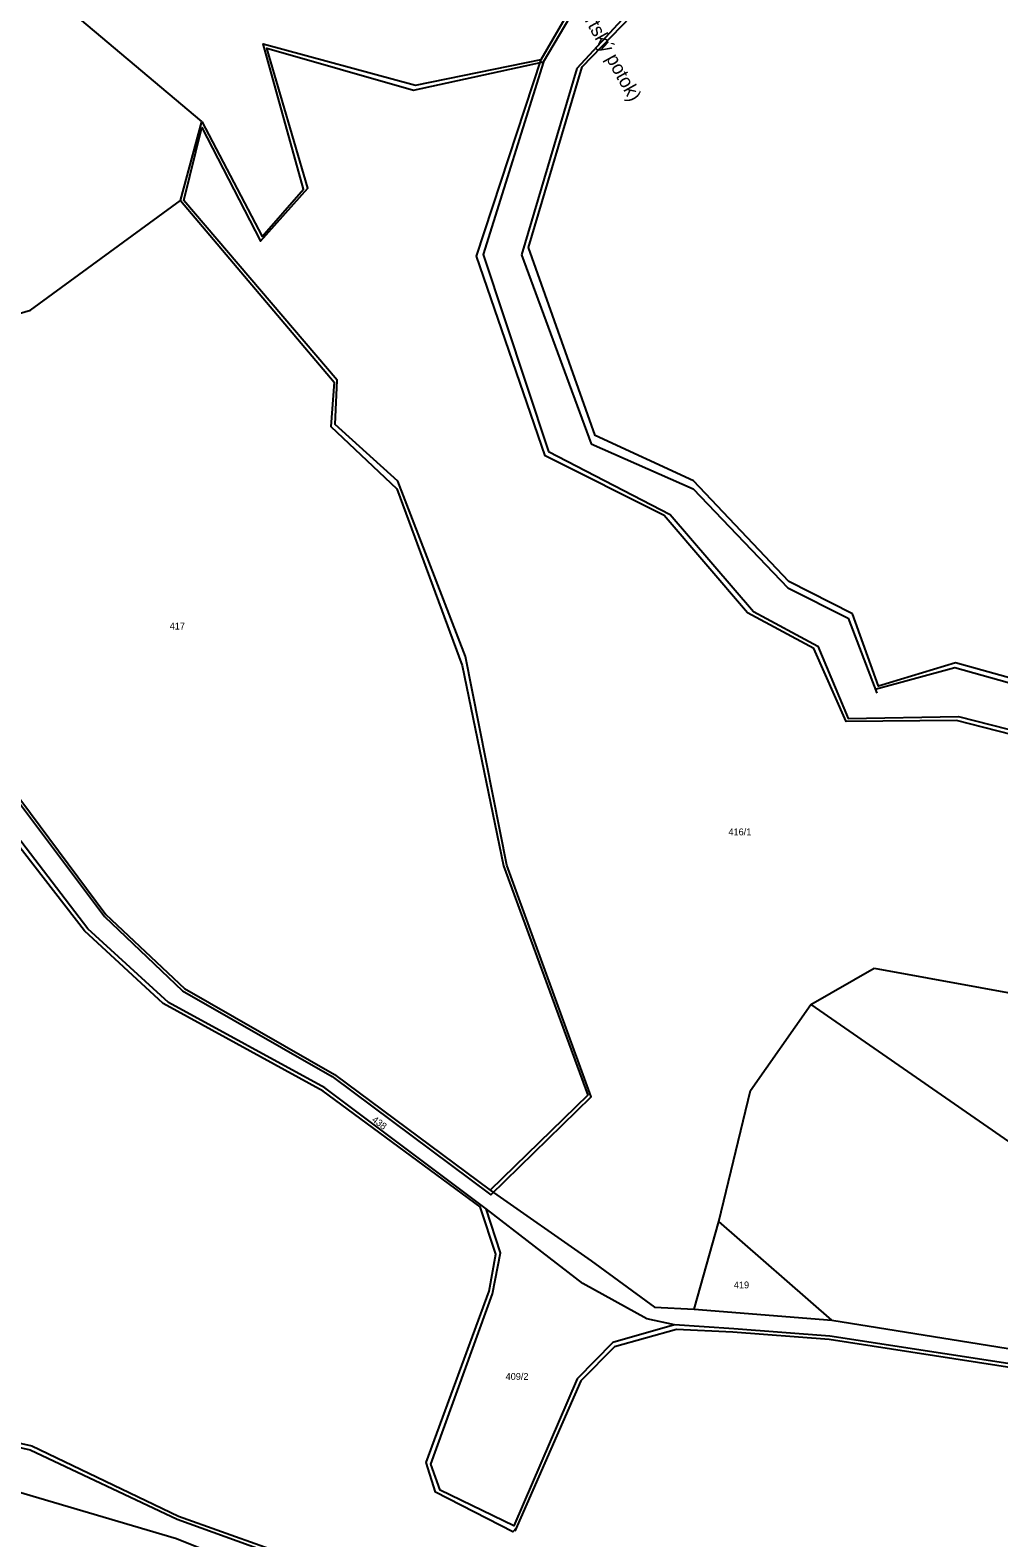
# Model space of a CAD drawing. Extents: x -880531 to -877616, y -1023932 to -1021350.
# Drawn here: x -880041.3 to -879800.4, y -1022593.9 to -1022219 of the extents above; entities that cross this region are included whole.
import ezdxf

# ---------------------------------------------------------------- set-up
doc = ezdxf.new("R2010")
doc.units = 0
for name, color, linetype in [('Hranice parcel', 7, 'Continuous'), ('Parcelní čísla', 7, 'Continuous'), ('Pop  PČ popisy', 7, 'Continuous'), ('Vnitřní kresba', 7, 'Continuous')]:
    doc.layers.add(name, color=color, linetype=linetype)

msp = doc.modelspace()

# ---------------------------------------------------------------- linework, layer by layer
at = {"layer": 'Hranice parcel'}
for p, q in [((-880003.96, -1022261.33), (-879998.66, -1022241.71)), ((-879836.8, -1022364.1), (-879852.62, -1022356.1)), ((-879876.21, -1022537.01), (-879870.02, -1022515.23)), ((-879841.96, -1022539.75), (-879870.02, -1022515.23)), ((-879876.21, -1022537.01), (-879841.96, -1022539.75))]:
    msp.add_line(p, q, dxfattribs=at)
for points in [[(-879998.66, -1022241.71), (-880052.08, -1022196.68), (-880086.25, -1022160.89), (-880089.28, -1022150.93), (-880085.05, -1022135.52)], [(-879852.62, -1022356.1), (-879876.34, -1022331.08), (-879900.8, -1022319.74), (-879917.41, -1022273.06), (-879904.07, -1022228.12), (-879891.86, -1022215.5), (-879913.95, -1022179.12), (-879927.16, -1022162.97), (-879953.53, -1022160.38), (-879979.51, -1022142.78), (-880011, -1022145.56), (-880011.84, -1022139.78)], [(-879914.25, -1022226.31), (-879906.81, -1022213.47), (-879922.39, -1022185.03), (-879929.69, -1022178.8), (-879958.73, -1022168.9), (-879984.23, -1022153.64), (-880001.2, -1022153.91)], [(-879998.66, -1022241.71), (-879983.68, -1022270.28), (-879973.36, -1022258.52), (-879983.36, -1022222.39), (-879945.5, -1022232.64), (-879914.25, -1022226.31)], [(-879633.8, -1022480.63), (-879660.6, -1022471.88), (-879677.81, -1022467.72), (-879699.12, -1022454.05), (-879720.69, -1022446.04), (-879736.48, -1022420.52), (-879771.92, -1022408.58), (-879783.4, -1022397.72), (-879810.92, -1022390.65), (-879838.37, -1022390.91), (-879846.45, -1022372.72), (-879862.92, -1022363.84), (-879883.64, -1022339.68), (-879913.23, -1022324.87), (-879930.34, -1022275.22), (-879914.25, -1022226.31)], [(-880095.42, -1022304.53), (-880041.25, -1022288.65), (-880003.96, -1022261.33)], [(-880003.96, -1022261.33), (-879965.77, -1022306.53), (-879966.58, -1022317.51), (-879950.15, -1022333.01), (-879933.89, -1022376.93), (-879923.6, -1022426.78), (-879902.64, -1022483.8), (-879926.96, -1022507.44)], [(-879927.95, -1022512.07), (-879968.07, -1022481.99), (-880006.9, -1022460.74), (-880027.04, -1022442.45), (-880059.05, -1022400.63), (-880086.76, -1022384.28), (-880123.5, -1022378.49), (-880154.72, -1022371.67), (-880202.4, -1022363.81)], [(-879770.1, -1022387.72), (-879811.18, -1022376.32), (-879830.38, -1022382.07), (-879836.8, -1022364.1)], [(-880120.79, -1022373.06), (-880085.05, -1022378.77), (-880053.08, -1022397.83), (-880022.5, -1022438.88), (-880002.99, -1022457.32), (-879965.63, -1022478.64), (-879926.96, -1022507.44)], [(-879870.02, -1022515.23), (-879862.14, -1022482.62), (-879847.14, -1022461.29)], [(-879847.14, -1022461.29), (-879797.97, -1022495.32), (-879652.28, -1022517.43)], [(-879926.96, -1022507.44), (-879901.83, -1022525.04), (-879886.09, -1022536.57), (-879876.21, -1022537.01)], [(-879881.1, -1022540.95), (-879896.44, -1022545.28), (-879905.27, -1022554.37), (-879921.06, -1022590.94), (-879939.38, -1022582.03), (-879941.72, -1022575.56), (-879926.35, -1022533.25), (-879924.39, -1022523), (-879927.95, -1022512.07)], [(-879881.1, -1022540.95), (-879888, -1022539.4), (-879903.88, -1022530.65), (-879927.95, -1022512.07)], [(-879700.32, -1022565.93), (-879708.74, -1022562.21), (-879723.29, -1022560.15), (-879752.61, -1022558.22), (-879785.23, -1022552.56), (-879842.49, -1022543.71), (-879866.35, -1022541.91), (-879881.1, -1022540.95)], [(-879841.96, -1022539.75), (-879784.65, -1022548.98), (-879752.14, -1022555.09), (-879721.69, -1022556.28), (-879706.73, -1022558.11), (-879695.24, -1022559.41), (-879680.86, -1022572.57), (-879675.16, -1022576.16)], [(-880166.5, -1022548.2), (-880166.5, -1022563), (-880091.71, -1022568.45), (-880004.96, -1022594.04), (-879942.81, -1022618.93)], [(-880109.86, -1022556.49), (-880041.33, -1022572.02), (-880004.82, -1022589.23), (-879971.92, -1022601.09), (-879941.5, -1022616.12)]]:
    msp.add_lwpolyline(points, dxfattribs=at)
at = {"layer": 'Vnitřní kresba'}
for p, q in [((-879905.4, -1022228.48), (-879919.17, -1022274.86)), ((-879919.17, -1022274.86), (-879901.77, -1022321.82)), ((-879901.77, -1022321.82), (-879876.48, -1022333)), ((-879876.48, -1022333), (-879852.93, -1022357.64)), ((-879852.93, -1022357.64), (-879837.91, -1022365.23)), ((-879837.91, -1022365.23), (-879830.78, -1022383.83)), ((-879847.14, -1022461.29), (-879831.44, -1022452.23)), ((-879831.44, -1022452.23), (-879783, -1022461.08))]:
    msp.add_line(p, q, dxfattribs=at)
for points in [[(-879913.63, -1022226.83), (-879905.68, -1022213.45), (-879922.21, -1022184.03), (-879929.53, -1022177.98), (-879958.94, -1022167.8), (-879984.07, -1022152.69), (-880014.44, -1022153.17), (-880020.32, -1022147.44), (-880023.98, -1022138.69), (-880027.31, -1022135.35), (-880031.29, -1022125.65), (-880036.54, -1022124.85)], [(-879914.9, -1022179.41), (-879893.18, -1022215.36), (-879905.4, -1022228.48)], [(-880201.71, -1022365.15), (-880196.14, -1022357.83), (-880120.3, -1022374.06), (-880084.72, -1022379.56), (-880053.24, -1022398.97), (-880022.87, -1022439.38), (-880003.47, -1022457.83), (-879966.2, -1022479.16), (-879926.77, -1022508.59), (-879901.81, -1022484.25), (-879922.79, -1022426.66), (-879933.03, -1022374.74), (-879949.86, -1022331.15), (-879965.49, -1022317.02), (-879964.96, -1022306.01), (-880003.12, -1022261.31), (-879998.66, -1022243.17), (-879984.04, -1022271.49), (-879972.27, -1022258.28), (-879982.45, -1022223.45), (-879946.03, -1022233.94)], [(-879946.03, -1022233.94), (-879913.63, -1022226.83), (-879928.65, -1022274.74), (-879912.42, -1022323.74)], [(-879912.42, -1022323.74), (-879882.14, -1022339.39), (-879861.47, -1022363.57), (-879845.41, -1022372.16), (-879837.93, -1022390.13), (-879810.43, -1022389.65), (-879782.15, -1022396.86), (-879771.34, -1022407.84), (-879735.56, -1022419.77), (-879719.82, -1022445.22), (-879697.88, -1022453.49), (-879677.21, -1022466.85), (-879660.2, -1022471.15), (-879634.44, -1022479.57)], [(-879831.15, -1022382.88), (-879811.34, -1022377.43), (-879771.18, -1022388.74)], [(-879920.52, -1022591.58), (-879921.27, -1022592.36), (-879940.51, -1022582.5), (-879942.89, -1022575.18), (-879927.15, -1022532.55), (-879925.56, -1022523.32), (-879929.38, -1022511.55), (-879968.48, -1022482.85), (-880008.23, -1022461.06), (-880027.79, -1022442.92), (-880060.18, -1022401.31), (-880087.53, -1022385.08)], [(-880146.98, -1022500.44), (-880097.84, -1022509.25), (-880108.97, -1022555.86), (-880040.89, -1022570.99), (-880004.48, -1022588.49), (-879972.36, -1022599.94)], [(-879842.62, -1022544.57), (-879866.57, -1022542.73), (-879880.56, -1022542.09), (-879895.99, -1022546.39), (-879904.41, -1022554.82), (-879920.79, -1022592.2)], [(-879714.02, -1022623.13), (-879708.26, -1022602.63), (-879698.24, -1022577.81), (-879700.94, -1022566.36), (-879708.89, -1022563.02), (-879723.21, -1022561.27), (-879752.94, -1022559.2), (-879785.38, -1022553.47), (-879842.62, -1022544.57)]]:
    msp.add_lwpolyline(points, dxfattribs=at)

# ---------------------------------------------------------------- texts
at = {"layer": 'Parcelní čísla'}
for s, p in [('417', (-880006.64, -1022368.03)), ('416/1', (-879867.67, -1022419.2)), ('419', (-879866.32, -1022531.85)), ('409/2', (-879923.09, -1022554.61))]:
    msp.add_text(s, height=1.7, dxfattribs=at).set_placement(p)
msp.add_text('438', height=1.7, rotation=323, dxfattribs=at).set_placement((-879956.491, -1022490.238))
at = {"layer": 'Pop  PČ popisy'}
msp.add_text('Lipoltovský potok (Kynžvartský potok)', height=3.4, rotation=299, dxfattribs=at).set_placement((-879928.959, -1022170.509))

doc.saveas('drawing.dxf')
